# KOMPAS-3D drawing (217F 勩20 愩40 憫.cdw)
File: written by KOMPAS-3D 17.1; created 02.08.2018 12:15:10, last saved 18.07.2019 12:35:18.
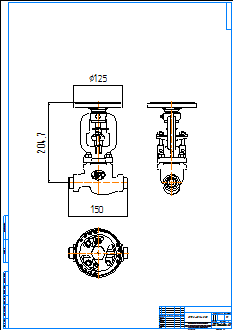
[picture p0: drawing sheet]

Sheet 1: A1, portrait

Title block, sheet 1: name: 217F Ду20 Ру40 СС; material: Внимание! Данный продукт является объектом авторского права ООО «Торговый Дом АДЛ». / Запрещается изменение, копирование, распространение / (в том числе путем копирования на другие сайты и ресурсы в Интернете) / или любое иное использование информации и объектов без предварительного / согласия правообладателя (ООО «Торговый Дом АДЛ»).; sheets: 1; organisation: ООО "Торговый дом АДЛ"; sheet format: A1; stored path: \\adlc.lan\data\АДЛ_ПКД\3D-модели\Поставщики\Zetkama\Вентили\217F\KOMPAS 2D\217F Ду20 Ру40 СС.cdw

Views: Вид 1, Проекционный вид 2, Проекционный вид 3
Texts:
  kka
  adl
Dimensions and other numbers on the sheet: 150; 204,7; 125; 1:1; 1; 217F Ду20 Ру40 СС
